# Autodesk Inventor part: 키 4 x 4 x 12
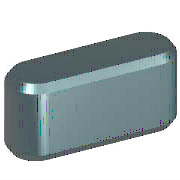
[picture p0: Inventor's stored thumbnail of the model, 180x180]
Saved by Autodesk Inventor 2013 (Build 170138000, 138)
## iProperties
IsCustomPart: 1
Created: 2012-02
Part Number: 키 4 x 4 x 12
Material: 강철, 연강
Description: 키 및 해당 키홈
Document SubType Name: Modeling
Standard: KS B 1311
Designer: mduedu
Standards Organization: KS
Language: ko-KR
Size Designation: 4 x 4 x 12
Categories: <MemberInstance><Categories><Category DisplayName="샤프트 부품" InternalName="7f7aeb1f-a693-4053-b835-cee3144e0d98" Mnemonic="SHFT"><Category DisplayName="키" Interna
Density: 1 g/cm^3
Author: mduedu
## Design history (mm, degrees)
workplane "Work Plane1"
workplane "Work Plane2"
sketch "스케치1"
  geometry: L1 (2, 2)-(10, 2); L2 (10, -2)-(2, -2); L3 (0, 9.4)-(0, -7.4) reference; L4 (-5, 0)-(30, 0) reference; L5 (12, 0)-(12, 7); A1 r 2 centre (2, 0) between (2, 2) and (2, -2); A2 r 2 centre (10, 0) between (10, -2) and (10, 2)
  constraints: 6 end point, 5 point on circle, 4 tangent, 3 point on line, 2 centre point, 1 horizontal, 1 parallel, 1 perpendicular
  dimensions: "d0" = 2 radius of A1 (= 0.5 x PB); "d13" = 2 radius of A2 (= 0.5 x PB); "d14" = 12 distance between parallel lines of L5 L3 (= NLG)
extrude "본체1" new body sketch "스케치1" taper "d3" = 0 deg; stored distance "d4" = 10
workplane "Work Plane3"
body "Solid1"
chamfer "모따기1" distance "d8" = 0.25 (= PHH); stored, may be unused: second distance "d9" = 0.25 (= PHH), angle "d15" = 45 deg
other parameters: "d1" = -2.5 (= -PNT), "d2" = 1.5 (= PH - PNT), "NLG" = 12 [user parameter; used in 3 equation terms], "PB" = 4 [user parameter; used in 2 equation terms], "PNT" = 2.5 [user parameter; used in 2 equation terms], "PH" = 4 [user parameter; used in 1 equation term], "PHH" = 0.25 [user parameter; used in 2 equation terms], "d10" = 0, "d16" = 0, "d17" = 0, "d18" = 0, "PLB2" = 12 (= NLG) [user parameter], "WDMAX" = 12 [user parameter], "PLB1" = 12 (= NLG) [user parameter], "RR" = 0.08 [user parameter], "PUEB" = 1.8 [user parameter]
